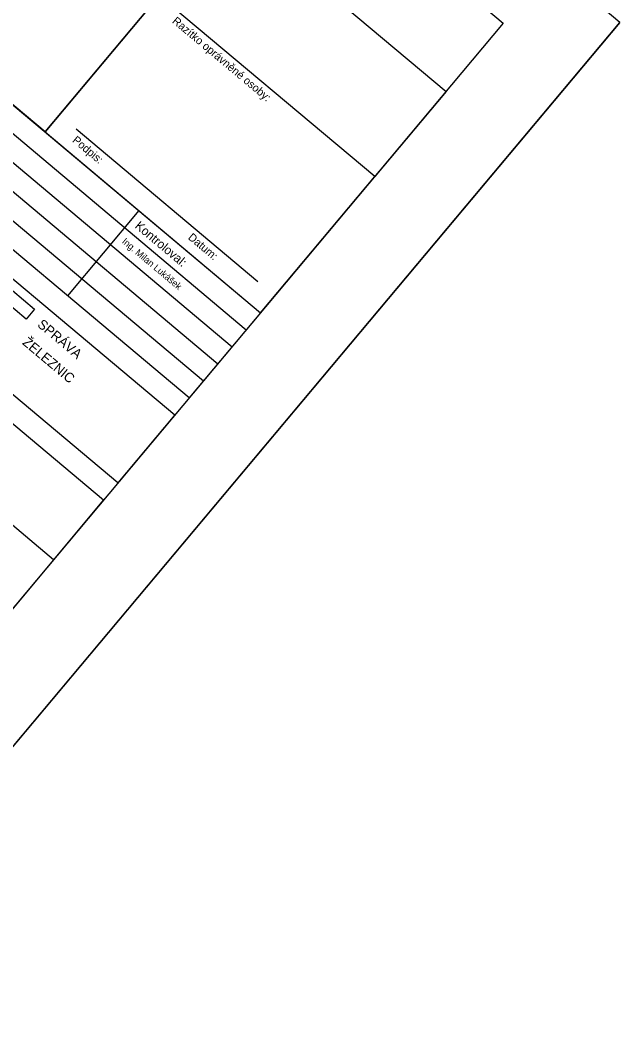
# Model space of a CAD drawing. Extents: x -653515 to -646779, y -1102358 to -1096033.
# Drawn here: x -648129 to -646779, y -1102358 to -1100078 of the extents above; entities that cross this region are included whole.
import ezdxf

# ---------------------------------------------------------------- set-up
doc = ezdxf.new("R2010")
doc.units = 0
for name, color, linetype in [('Default', 7, 'Continuous'), ('pomocná - netisk 2', 7, 'Continuous'), ('Rozpiska_Logo', 7, 'Continuous'), ('Rozpiska_pola_3', 7, 'Continuous'), ('Rozpiska_pole_1', 7, 'Continuous'), ('Rozpiska_pole_2', 7, 'Continuous'), ('Rozpiska_pole_4', 7, 'Continuous'), ('Rozpiska_pole_5', 7, 'Continuous'), ('Rozpiska_pole_6', 7, 'Continuous')]:
    doc.layers.add(name, color=color, linetype=linetype)

msp = doc.modelspace()

# ---------------------------------------------------------------- linework, layer by layer
at = {"layer": 'Default'}
msp.add_line((-648073.6, -1100328.2), (-647655.8, -1099830.3), dxfattribs=at)
at = {"layer": 'pomocná - netisk 2'}
msp.add_line((-646779.5, -1100082.6), (-648688.6, -1102357.8), dxfattribs=at)
msp.add_lwpolyline([(-651605.6, -1096033), (-653514.6, -1098308.2), (-648688.6, -1102357.8), (-646779.5, -1100082.6)], close=True, dxfattribs=at)
at = {"layer": 'Rozpiska_Logo'}
msp.add_lwpolyline([(-648221.9, -1100622.7), (-648097.1, -1100727.4), (-648115.9, -1100749.9), (-648240.8, -1100645.1)], close=True, dxfattribs=at)
at = {"layer": 'Rozpiska_pola_3'}
msp.add_line((-648003.2, -1100322), (-647594.5, -1100665), dxfattribs=at)
at = {"layer": 'Rozpiska_pole_1'}
msp.add_lwpolyline([(-648344.2, -1098991.5), (-647042, -1100084.3), (-648745.4, -1102114.3), (-650047.6, -1101021.6)], close=True, dxfattribs=at)
at = {"layer": 'Rozpiska_pole_2'}
for points in [[(-648633.5, -1099336.3), (-647816.5, -1100021.8), (-648073.6, -1100328.2), (-648890.6, -1099642.7)], [(-647655.8, -1099830.3), (-647170.5, -1100237.5), (-647331.2, -1100429), (-647816.5, -1100021.8)], [(-647331.2, -1100429), (-647816.5, -1100021.8), (-648073.6, -1100328.2), (-647588.3, -1100735.4)]]:
    msp.add_lwpolyline(points, close=True, dxfattribs=at)
at = {"layer": 'Rozpiska_pole_4'}
for p, q in [((-648922.8, -1099681), (-647620.5, -1100773.7)), ((-648954.9, -1099719.3), (-647652.6, -1100812)), ((-648987, -1099757.6), (-647684.8, -1100850.3)), ((-649019.2, -1099795.9), (-647716.9, -1100888.6)), ((-648022.5, -1100697.5), (-647861.8, -1100505.9))]:
    msp.add_line(p, q, dxfattribs=at)
msp.add_lwpolyline([(-648890.6, -1099642.7), (-647588.3, -1100735.4), (-647749, -1100926.9), (-649051.3, -1099834.2)], close=True, dxfattribs=at)
at = {"layer": 'Rozpiska_pole_5'}
msp.add_lwpolyline([(-649083.5, -1099872.5), (-647781.2, -1100965.2), (-647909.7, -1101118.4), (-649212, -1100025.7)], close=True, dxfattribs=at)
at = {"layer": 'Rozpiska_pole_6'}
msp.add_line((-649356.6, -1100198.1), (-648054.4, -1101290.8), dxfattribs=at)
msp.add_lwpolyline([(-649244.2, -1100064), (-647941.9, -1101156.7), (-648199, -1101463.2), (-649501.3, -1100370.4)], close=True, dxfattribs=at)

# ---------------------------------------------------------------- texts
at = {"layer": 'Rozpiska_pola_3'}
for s, p in [('Razítko oprávněné osoby:', (-647788.6, -1100081.8)), ('Podpis:', (-648013.5, -1100349.9)), ('Datum:', (-647753.1, -1100568.5))]:
    msp.add_text(s, height=18, rotation=320, dxfattribs=at).set_placement(p)
at = {"layer": 'Rozpiska_pole_4'}
for s, height, p in [('Kontroloval:', 20, (-647872.8, -1100543)), ('Ing. Milan Lukášek', 15, (-647901.7, -1100577.5))]:
    msp.add_text(s, height=height, rotation=320, dxfattribs=at).set_placement(p)
at = {"layer": 'Rozpiska_pole_6'}
for s, p in [('SPRÁVA', (-648092.6, -1100764.9)), ('ŽELEZNIC', (-648126.3, -1100805.1))]:
    msp.add_text(s, height=21.83, rotation=320, dxfattribs=at).set_placement(p)

doc.saveas('drawing.dxf')
